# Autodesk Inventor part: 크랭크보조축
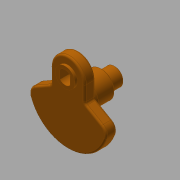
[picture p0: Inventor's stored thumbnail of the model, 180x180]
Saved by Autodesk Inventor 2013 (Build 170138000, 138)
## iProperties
Created: 2016-11
Part Number: 크랭크보조축
Material: 강철, 탄소
Document SubType Name: Modeling
Designer: mduedu
Density: 7.87 g/cm^3
Mass: 629.243 g
Surface Area: 163.688 cm^2
Volume: 79.9546 cm^3
Author: mduedu
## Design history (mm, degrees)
sketch "스케치1" dims "d8" = 65
  geometry: L1 (-19, 26.368)-(-19, 8.368); L2 (-19, 8.368)-(-44.545, -6.381); L3 (0, 26.368)-(0, -45); L4 (19, 26.368)-(19, 8.368); L5 (19, 8.368)-(44.545, -6.381); C1 r 10 at (0, 0); C2 r 17.5 at (0, 0); A1 r 45 centre (0, 0) between (-44.545, -6.381) and (0, -45); A2 r 19 centre (0, 26.368) between (0, 45.368) and (-19, 26.368); A3 r 19 centre (0, 26.368) between (19, 26.368) and (0, 45.368); A4 r 45 centre (0, 0) between (0, -45) and (44.545, -6.381); 2 further points
  constraints: 10 end point, 8 point on circle, 6 centre point, 4 coincident, 3 symmetric about line, 2 point on line, 1 parallel, 1 tangent, 1 vertical, 1 vertical alignment, 5 other
  dimensions: "d1" = 20 diameter of C1; "d2" = 35 diameter of C2; "d4" = 18 distance of L1.start L1.end; "d5" = 120 deg angle of L2 L1; "d6" = 45 radius of A1; "d9" = 19 radius of A2
extrude "돌출1" new body sketch "스케치1" distance "d10" = 12; taper "d11" = 0 deg
sketch "스케치2"
  geometry: C1 r 7.5 at (0, 26.368); C2 r 11 at (0, 26.368); A1 r 19 centre (0, 26.368) between (19, 26.368) and (-19, 26.368) reference; 1 further point
  constraints: 2 centre point, 2 coincident
  dimensions: "d16" = 15 diameter of C1; "d17" = 22 diameter of C2
extrude "돌출10" join sketch "스케치1" distance "d46" = 5; taper "d47" = 0 deg
extrude "돌출11" join sketch "스케치1" distance "d48" = 41; taper "d49" = 0 deg
extrude "돌출12" join sketch "스케치2" distance "d50" = 3; taper "d51" = 0 deg
extrude "돌출13" cut sketch "스케치2" stored distance "d52" = 3; taper "d53" = 0 deg
sketch "스케치7"
  geometry: L1 (5.75, -4.815)-(-5.75, -4.815); L2 (-5.75, -4.815)-(-5.75, 4.815); L3 (-5.75, 4.815)-(5.75, 4.815); L4 (5.75, 4.815)-(5.75, -4.815); L5 (5.75, -4.815)-(-5.75, 4.815); L6 (-5.75, -4.815)-(5.75, 4.815); A1 r 7.5 centre (0, 0) between (-5.75, 4.815) and (-5.75, -4.815); A2 r 7.5 centre (0, 0) between (5.75, -4.815) and (5.75, 4.815); 2 further points
  constraints: 12 end point, 4 point on circle, 2 centre point, 2 midpoint, 2 parallel, 1 coincident, 1 horizontal, 1 perpendicular, 2 other
  dimensions: "d54" = 11.5 distance of L2.end L3.end
extrude "돌출14" join sketch "스케치7" stored distance "d56" = 40.75; taper "d57" = 0 deg
sketch "스케치8"
  geometry: C1 r 17.5 at (0, 0) reference; C2 r 15 at (0, 0); 1 further point
  constraints: 1 centre point, 1 coincident
  dimensions: "d58" = 30 diameter of C2
extrude "돌출15" join sketch "스케치8" distance "d59" = 21; taper "d60" = 0 deg
chamfer "모따기3" distance "d61" = 1; stored, may be unused: second distance "d62" = 2, angle "d63" = 45 deg
fillet "모깎기3" dims "d64" = 3, "d65" = 10
fillet "모깎기4" dims "d66" = 2
node "솔리드1"
other parameters: "d3" = 38
